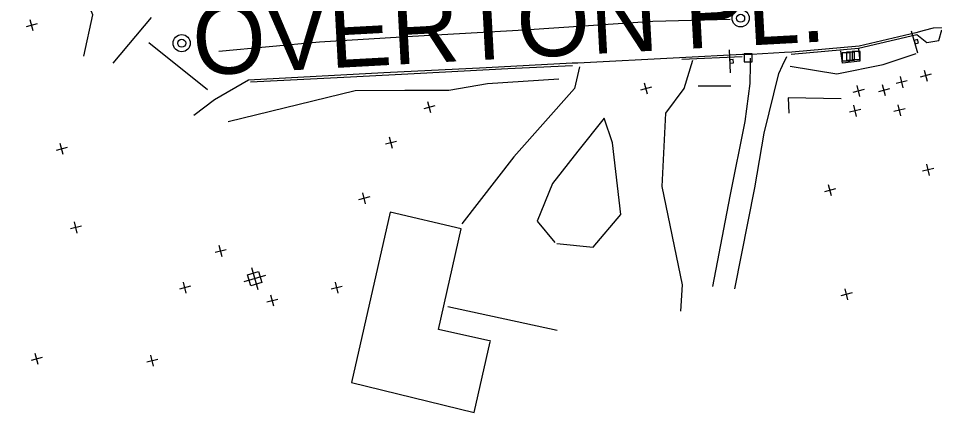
# Model space of a CAD drawing. Extents: x 4711259 to 4716401, y 890074 to 892728.
# Drawn here: x 4714377.1 to 4714778.1, y 890871 to 891043.5 of the extents above; entities that cross this region are included whole.
import ezdxf

# ---------------------------------------------------------------- set-up
doc = ezdxf.new("R2010")
doc.units = 0
for name, color, linetype in [('E_HY_STORM_MH', 7, 'Continuous'), ('E_RDWY_PHOTOG_Eave', 7, 'Continuous'), ('E_RDWY_ROAD_Curb', 7, 'Continuous'), ('E_RDWY_ROAD_EdgeAsph', 7, 'Continuous'), ('E_RDWY_ROAD_EdgeConc', 7, 'Continuous'), ('E_RDWY_ROAD_EdgeGravel', 7, 'Continuous'), ('E_RDWY_ROAD_Mailbox', 7, 'Continuous'), ('E_RDWY_ROAD_NameTx', 7, 'Continuous'), ('E_RDWY_ROAD_Sidewalk', 7, 'Continuous'), ('E_RDWY_ROAD_TBofCurb', 7, 'Continuous'), ('E_TERR_DTM_BrkLines', 7, 'Continuous'), ('E_TERR_DTM_RandomPt', 7, 'Continuous'), ('E_TRAF_SIGN_PublicSign', 7, 'Continuous'), ('E_UTIL_ELEC_POLE', 7, 'Continuous')]:
    doc.layers.add(name, color=color, linetype=linetype)

msp = doc.modelspace()

# ---------------------------------------------------------------- linework, layer by layer
at = {"layer": 'E_HY_STORM_MH'}
for centre, radius in [((4714693.22, 891043.5), 3.75), ((4714693.22, 891043.5), 1.76), ((4714448.58, 891032.59), 3.75), ((4714448.58, 891032.59), 1.76)]:
    msp.add_circle(centre, radius, dxfattribs=at)
at = {"layer": 'E_RDWY_PHOTOG_Eave'}
msp.add_lwpolyline([(4714583.89, 890902.21), (4714560.98, 890907.39), (4714570.88, 890951.31), (4714539.87, 890958.6), (4714522.85, 890884.1), (4714576.53, 890870.95), (4714583.6, 890902)], dxfattribs=at)
at = {"layer": 'E_RDWY_ROAD_Curb'}
msp.add_lwpolyline([(4714794.5, 891030.18), (4714787.19, 891037.94), (4714781.47, 891039.34), (4714777.5, 891039.18), (4714773.52, 891038.19), (4714769.87, 891037.1), (4714745.06, 891031.26), (4714715.63, 891028.71), (4714712.38, 891028.49), (4714697.92, 891027.61), (4714694.04, 891027.64), (4714666.46, 891026.17), (4714621.96, 891023.85), (4714619.54, 891023.9), (4714581.88, 891021.84), (4714537.04, 891019.62), (4714477.81, 891016.45)], dxfattribs=at)
at = {"layer": 'E_RDWY_ROAD_EdgeAsph'}
for points in [[(4714435.27, 891043.86), (4714418.47, 891023.86)], [(4714667.11, 890915.3), (4714667.83, 890926.89), (4714658.84, 890969.88), (4714660.41, 891002.04), (4714668.57, 891012.74), (4714672.31, 891025.24)], [(4714622.64, 891022.2), (4714620.46, 891012.76), (4714593.95, 890982.86), (4714571.12, 890953.62)], [(4714477.81, 891016.45), (4714462.91, 891007.76), (4714453.86, 891000.93)], [(4714612.7, 890944.89), (4714628.73, 890943.36), (4714640.72, 890957.63), (4714637.2, 890989.03), (4714633.42, 890999.76), (4714622.03, 890985.34), (4714610.92, 890971.25), (4714604.23, 890954.67), (4714611.96, 890945.35)], [(4714565.05, 890917.42), (4714612.95, 890907.11)]]:
    msp.add_lwpolyline(points, dxfattribs=at)
at = {"layer": 'E_RDWY_ROAD_EdgeConc'}
msp.add_lwpolyline([(4714744.8, 891030.14), (4714745.43, 891024.7), (4714737.75, 891023.85), (4714737.02, 891029.3)], dxfattribs=at)
at = {"layer": 'E_RDWY_ROAD_EdgeGravel'}
for points in [[(4714697.33, 891026.11), (4714697.46, 891023.09), (4714697.25, 891014.96), (4714695.12, 890998.36), (4714688.42, 890965.72), (4714680.95, 890926.08)], [(4714690.72, 890925.17), (4714699.38, 890969.37), (4714703.58, 890993.19), (4714710, 891019.41), (4714711.57, 891022.89), (4714713.45, 891026.74)]]:
    msp.add_lwpolyline(points, dxfattribs=at)
at = {"layer": 'E_RDWY_ROAD_Mailbox'}
for points in [[(4714698.31, 891027.94), (4714694.81, 891027.97), (4714694.78, 891024.47), (4714698.28, 891024.44)], [(4714741.13, 891024.85), (4714741.12, 891028.35), (4714737.62, 891028.33), (4714737.63, 891024.83)], [(4714743.06, 891025.11), (4714743.05, 891028.61), (4714739.55, 891028.6), (4714739.56, 891025.1)], [(4714745.49, 891025.52), (4714745.48, 891029.02), (4714741.98, 891029.01), (4714741.99, 891025.51)]]:
    msp.add_lwpolyline(points, close=True, dxfattribs=at)
at = {"layer": 'E_RDWY_ROAD_Sidewalk'}
msp.add_lwpolyline([(4714770.4, 891036.35), (4714774.68, 891032.83), (4714779.92, 891033.78), (4714781.25, 891038.5)], dxfattribs=at)
at = {"layer": 'E_RDWY_ROAD_TBofCurb'}
for points in [[(4714715.27, 891027.79), (4714744.81, 891030.38), (4714770.4, 891036.35)], [(4714693.83, 891026.66), (4714667.55, 891025.5)], [(4714478.63, 891015.64), (4714522.42, 891017.87), (4714553.12, 891019.45), (4714591.33, 891021.52), (4714619.67, 891022.78)]]:
    msp.add_lwpolyline(points, dxfattribs=at)
at = {"layer": 'E_TERR_DTM_BrkLines'}
for points in [[(4714405.8, 891026.88), (4714409.67, 891044.94), (4714403.38, 891060.41), (4714391.71, 891072.23), (4714375.46, 891087.37), (4714356.05, 891097.25)], [(4714464.86, 891029.08), (4714508.86, 891033.19), (4714549.55, 891035.69), (4714598.51, 891038.44), (4714654.74, 891042.22), (4714688.66, 891043.18)], [(4714434.12, 891032.84), (4714459.91, 891012.31)], [(4714714.89, 891022.48), (4714735.3, 891019.24), (4714755.64, 891023.3), (4714770.03, 891028.03)], [(4714613.71, 891016.88), (4714582.48, 891014.75), (4714565.54, 891011.96), (4714546.29, 891011.85), (4714524.45, 891011.81), (4714468.96, 890998.18)], [(4714688.9, 891013.84), (4714674.63, 891013.79)], [(4714737.22, 891008.21), (4714714.08, 891008.63), (4714714.38, 891001.97)]]:
    msp.add_lwpolyline(points, dxfattribs=at)
at = {"layer": 'E_TERR_DTM_RandomPt'}
for p, q in [((4714383.53, 891037.97), (4714382.28, 891042.81)), ((4714385.33, 891041.01), (4714380.49, 891039.76)), ((4714763.01, 891017.97), (4714764.26, 891013.13)), ((4714776.66, 891019.03), (4714771.82, 891017.78)), ((4714773.62, 891020.83), (4714774.87, 891015.98)), ((4714654.19, 891013.36), (4714649.35, 891012.11)), ((4714652.39, 891010.32), (4714651.14, 891015.16)), ((4714745.43, 891009.23), (4714744.18, 891014.07)), ((4714756.62, 891009.58), (4714755.37, 891014.42)), ((4714766.06, 891016.17), (4714761.22, 891014.92)), ((4714747.23, 891012.28), (4714742.39, 891011.02)), ((4714758.41, 891012.63), (4714753.57, 891011.38)), ((4714559.4, 891005.14), (4714554.55, 891003.89)), ((4714557.6, 891002.09), (4714556.35, 891006.94)), ((4714743.96, 891000.57), (4714742.71, 891005.41)), ((4714763.39, 891000.85), (4714762.14, 891005.69)), ((4714745.76, 891003.61), (4714740.92, 891002.36)), ((4714765.18, 891003.9), (4714760.34, 891002.65)), ((4714542.63, 890989.62), (4714537.79, 890988.37)), ((4714540.84, 890986.58), (4714539.59, 890991.42)), ((4714398.5, 890986.95), (4714393.66, 890985.7)), ((4714396.7, 890983.9), (4714395.45, 890988.74)), ((4714777.71, 890977.8), (4714772.86, 890976.55)), ((4714775.91, 890974.75), (4714774.66, 890979.6)), ((4714732.92, 890965.8), (4714731.67, 890970.64)), ((4714530.86, 890965.38), (4714526.02, 890964.13)), ((4714529.07, 890962.33), (4714527.82, 890967.17)), ((4714734.72, 890968.85), (4714729.88, 890967.6)), ((4714402.88, 890949.54), (4714401.62, 890954.38)), ((4714404.67, 890952.59), (4714399.83, 890951.34)), ((4714468.03, 890942.23), (4714463.19, 890940.98)), ((4714466.24, 890939.19), (4714464.99, 890944.03)), ((4714452.38, 890926.25), (4714447.54, 890925)), ((4714450.58, 890923.2), (4714449.33, 890928.04)), ((4714518.88, 890926.21), (4714514.04, 890924.96)), ((4714517.08, 890923.17), (4714515.83, 890928.01)), ((4714740.18, 890920.28), (4714738.93, 890925.12)), ((4714488.87, 890917.48), (4714487.62, 890922.33)), ((4714741.97, 890923.33), (4714737.13, 890922.08)), ((4714490.67, 890920.53), (4714485.82, 890919.28)), ((4714385.75, 890892.03), (4714384.5, 890896.87)), ((4714387.54, 890895.07), (4714382.7, 890893.82)), ((4714438.09, 890894.27), (4714433.25, 890893.02)), ((4714436.3, 890891.23), (4714435.04, 890896.07))]:
    msp.add_line(p, q, dxfattribs=at)
at = {"layer": 'E_TRAF_SIGN_PublicSign'}
for p, q in [((4714770.73, 891028.29), (4714767.99, 891037.91)), ((4714770.08, 891033.31), (4714770.08, 891033.31)), ((4714688.72, 891019.64), (4714688.3, 891029.63)), ((4714689.26, 891024.66), (4714689.26, 891024.66))]:
    msp.add_line(p, q, dxfattribs=at)
for points in [[(4714769.57, 891032.38), (4714771.01, 891032.79), (4714770.6, 891034.23), (4714769.15, 891033.82)], [(4714688.54, 891023.88), (4714690.04, 891023.95), (4714689.97, 891025.44), (4714688.48, 891025.38)]]:
    msp.add_lwpolyline(points, close=True, dxfattribs=at)
at = {"layer": 'E_UTIL_ELEC_POLE'}
for p, q in [((4714479.12, 890934.39), (4714481.91, 890924.79)), ((4714485.32, 890930.98), (4714475.72, 890928.19))]:
    msp.add_line(p, q, dxfattribs=at)
for points in [[(4714482.22, 890932.69), (4714483.62, 890927.89), (4714478.82, 890926.49), (4714477.42, 890931.29)], [(4714483.62, 890927.89), (4714478.82, 890926.49), (4714477.42, 890931.29), (4714482.22, 890932.69)]]:
    msp.add_lwpolyline(points, close=True, dxfattribs=at)

# ---------------------------------------------------------------- texts
at = {"layer": 'E_RDWY_ROAD_NameTx'}
msp.add_text('OVERTON PL.', height=30.8399, rotation=3.1051, dxfattribs=at).set_placement((4714454.1, 891018.41))

doc.saveas('drawing.dxf')
